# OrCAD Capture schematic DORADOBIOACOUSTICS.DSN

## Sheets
1 4 MiniWBT Wiring: size Custom; title: Dorado Bioacoustics System; rev: A; note: 100221282
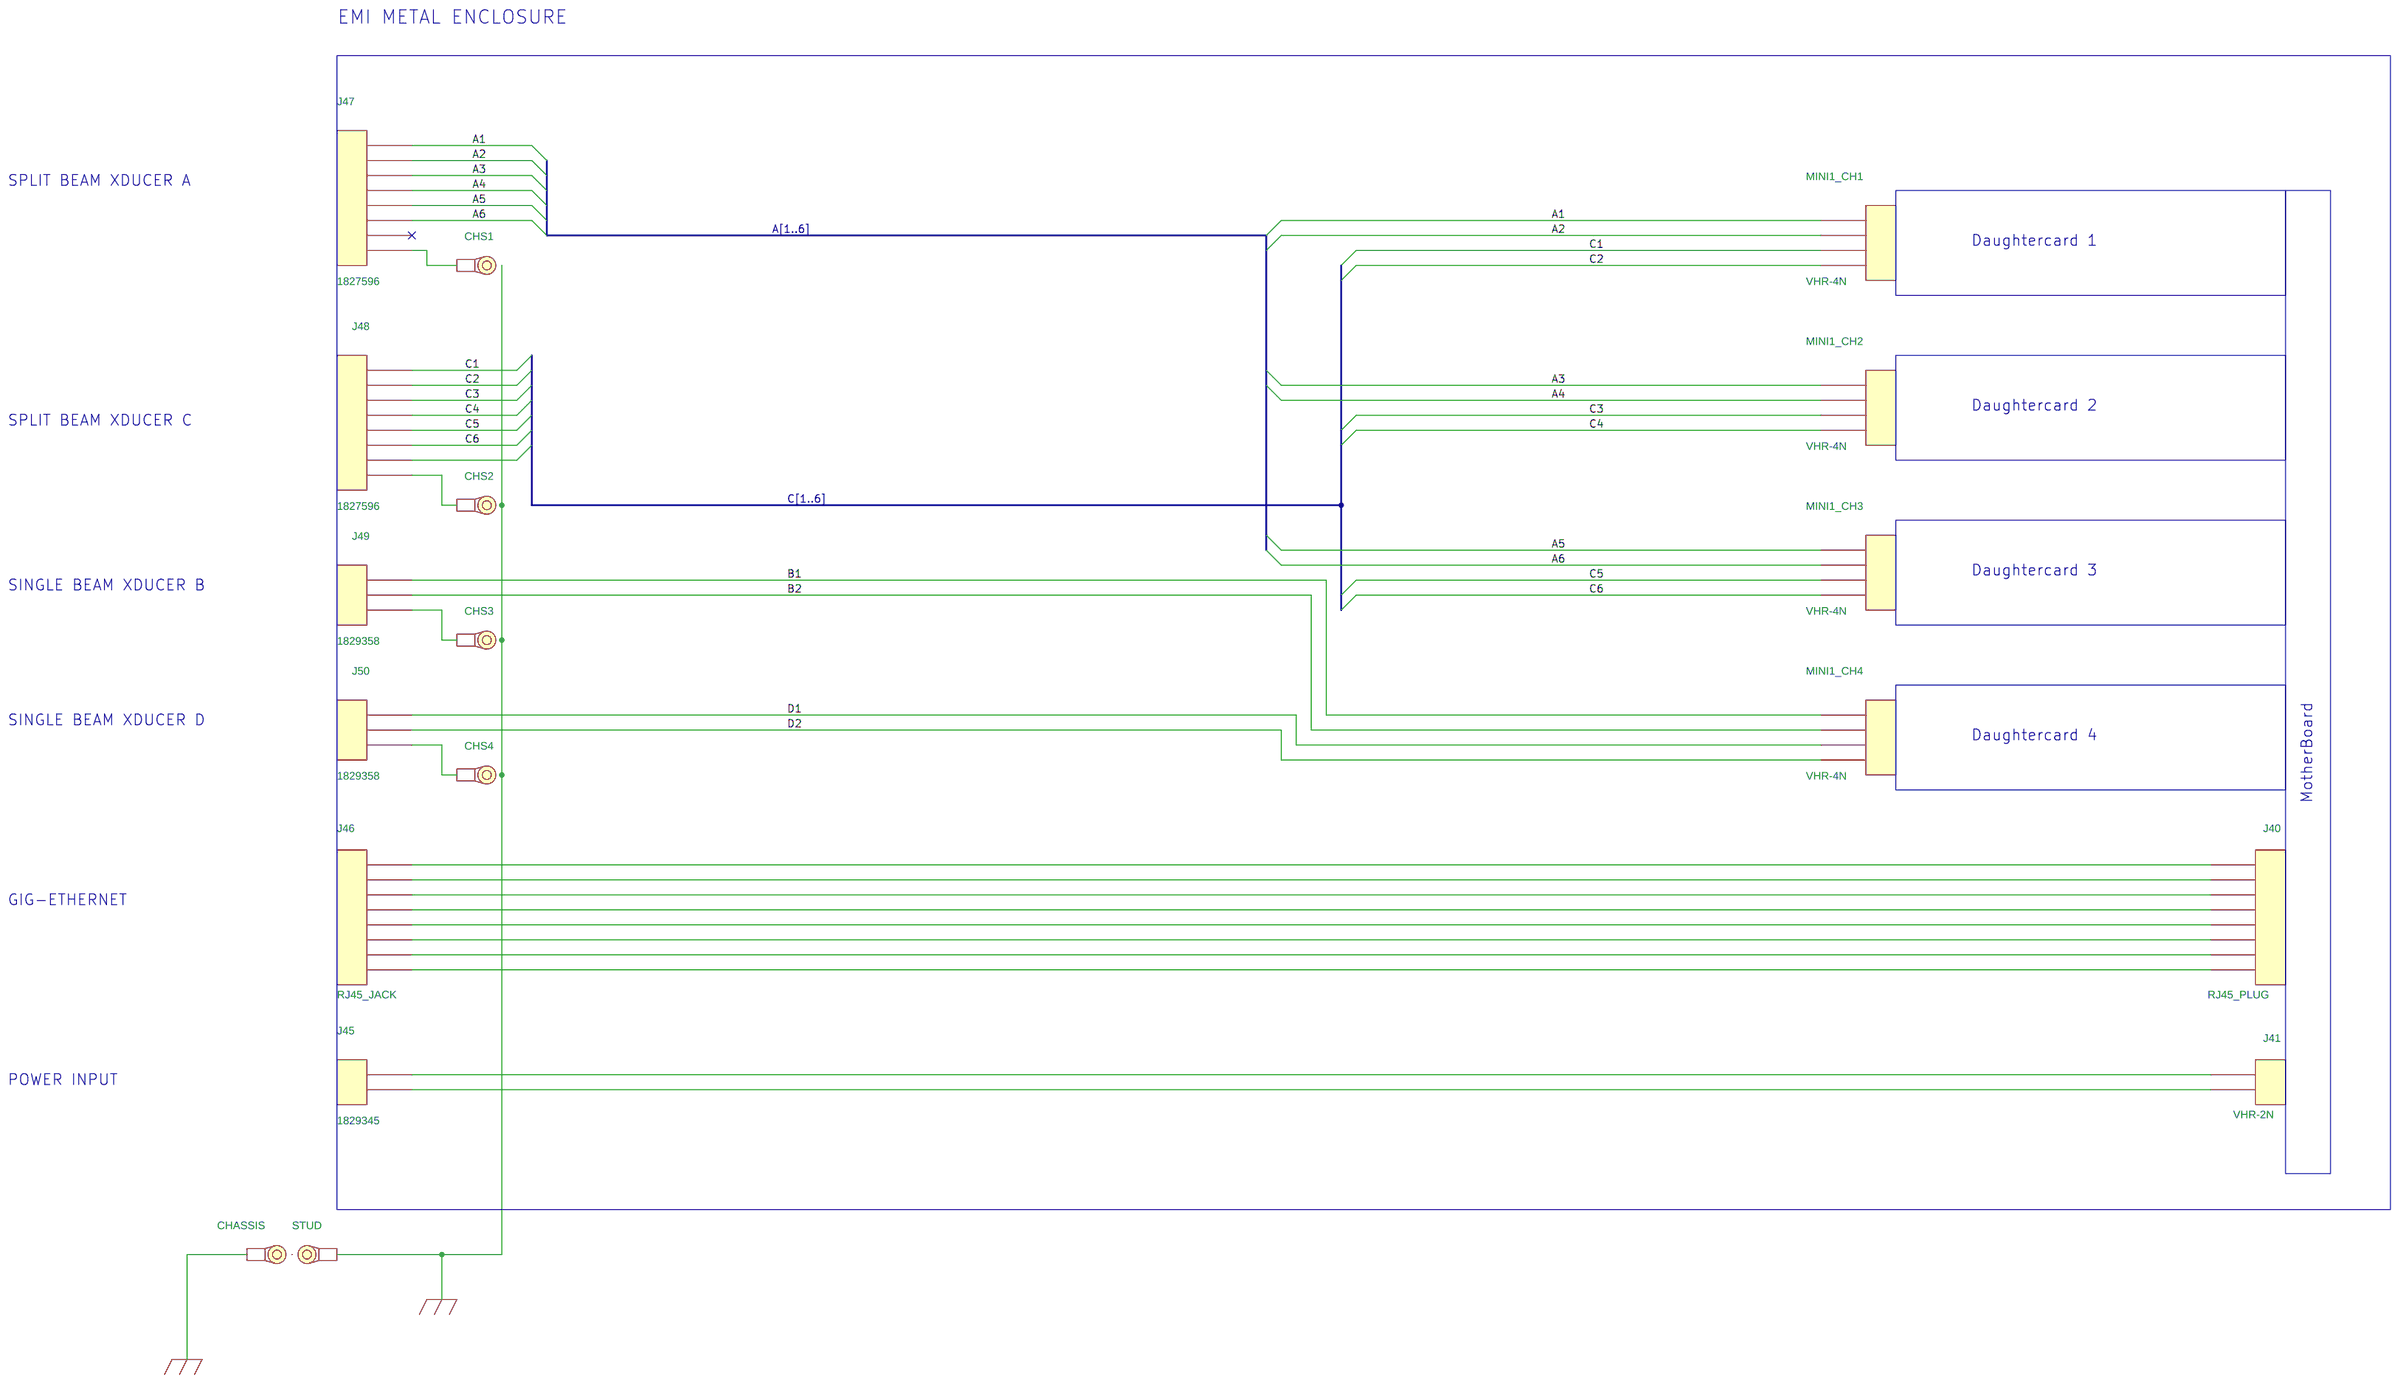
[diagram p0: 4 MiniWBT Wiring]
2 1 System Concept: size Custom; note: 100221222
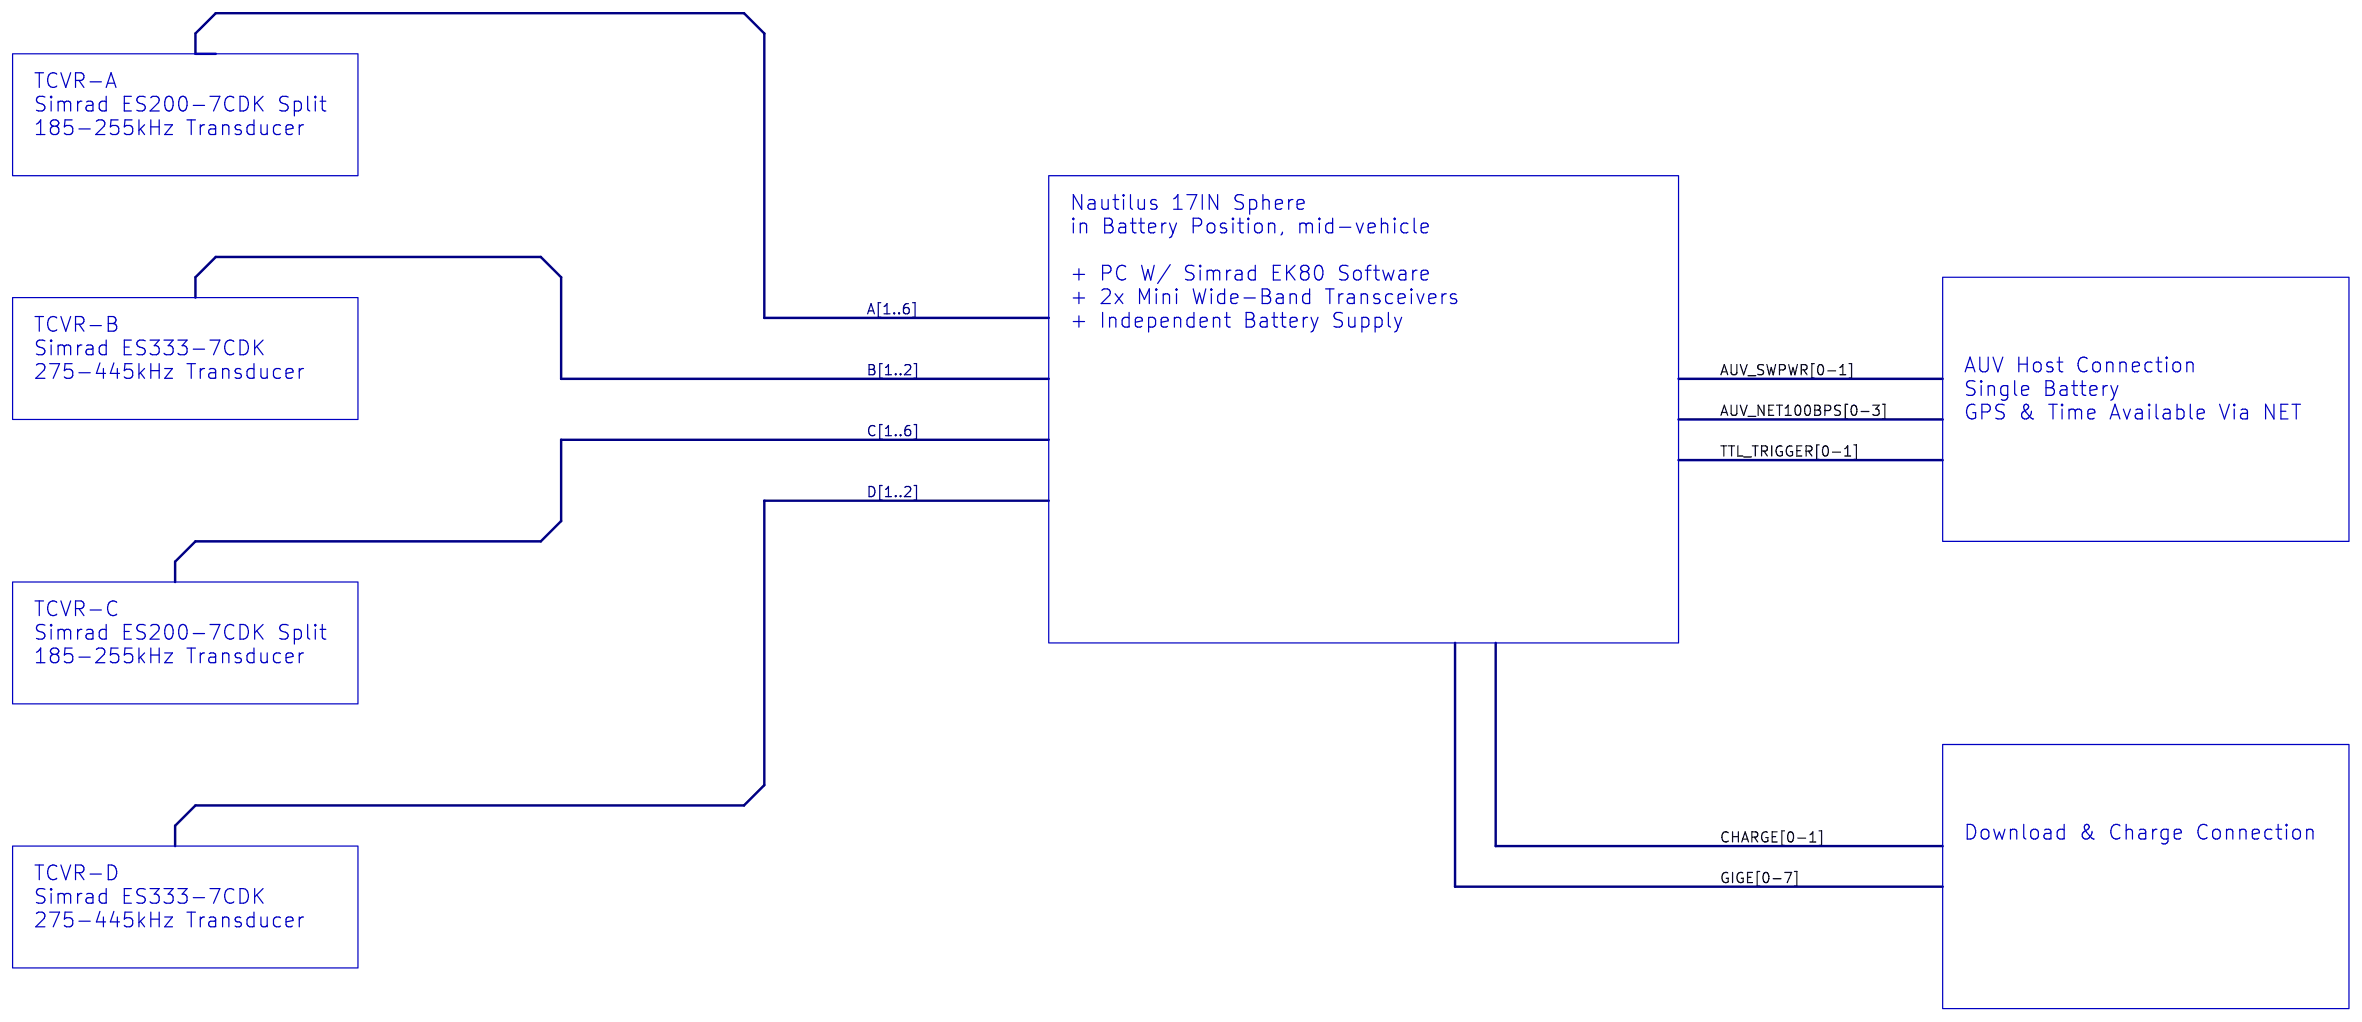
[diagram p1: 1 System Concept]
3 2 Subsea Cabling: size Custom; note: 100221222
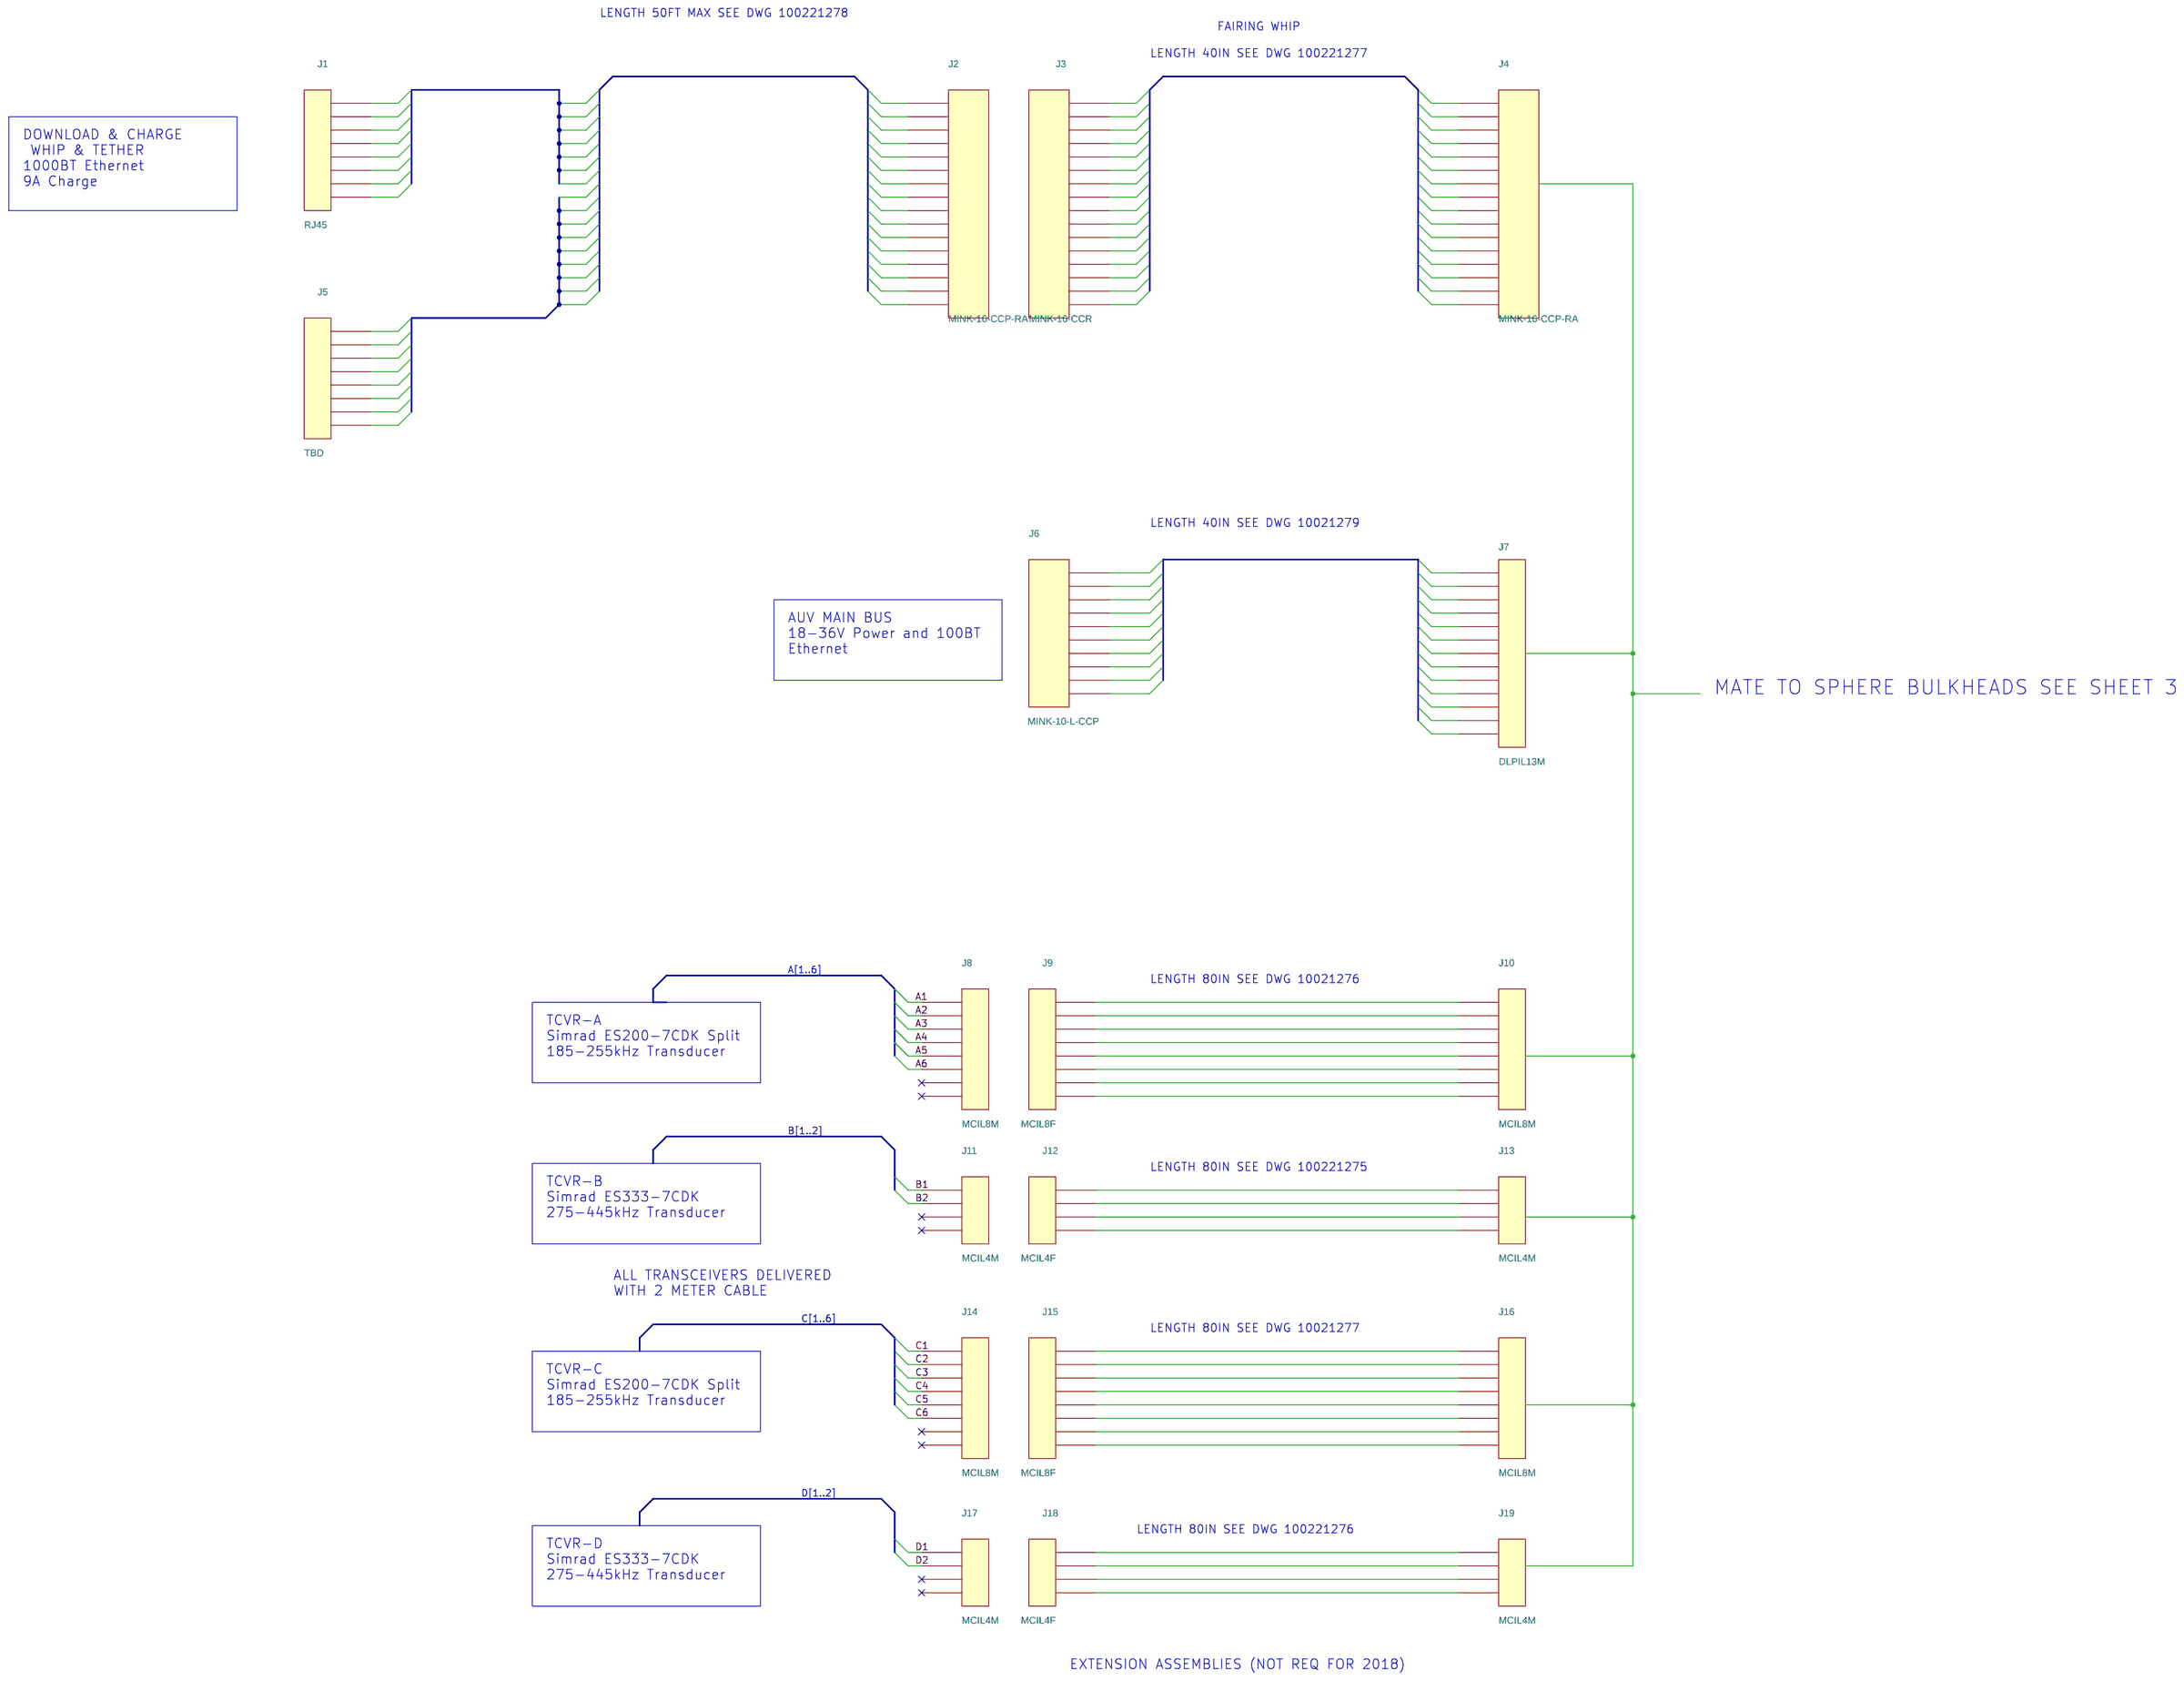
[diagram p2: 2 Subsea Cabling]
4 3 Sphere Wiring: size Custom; note: 100221222
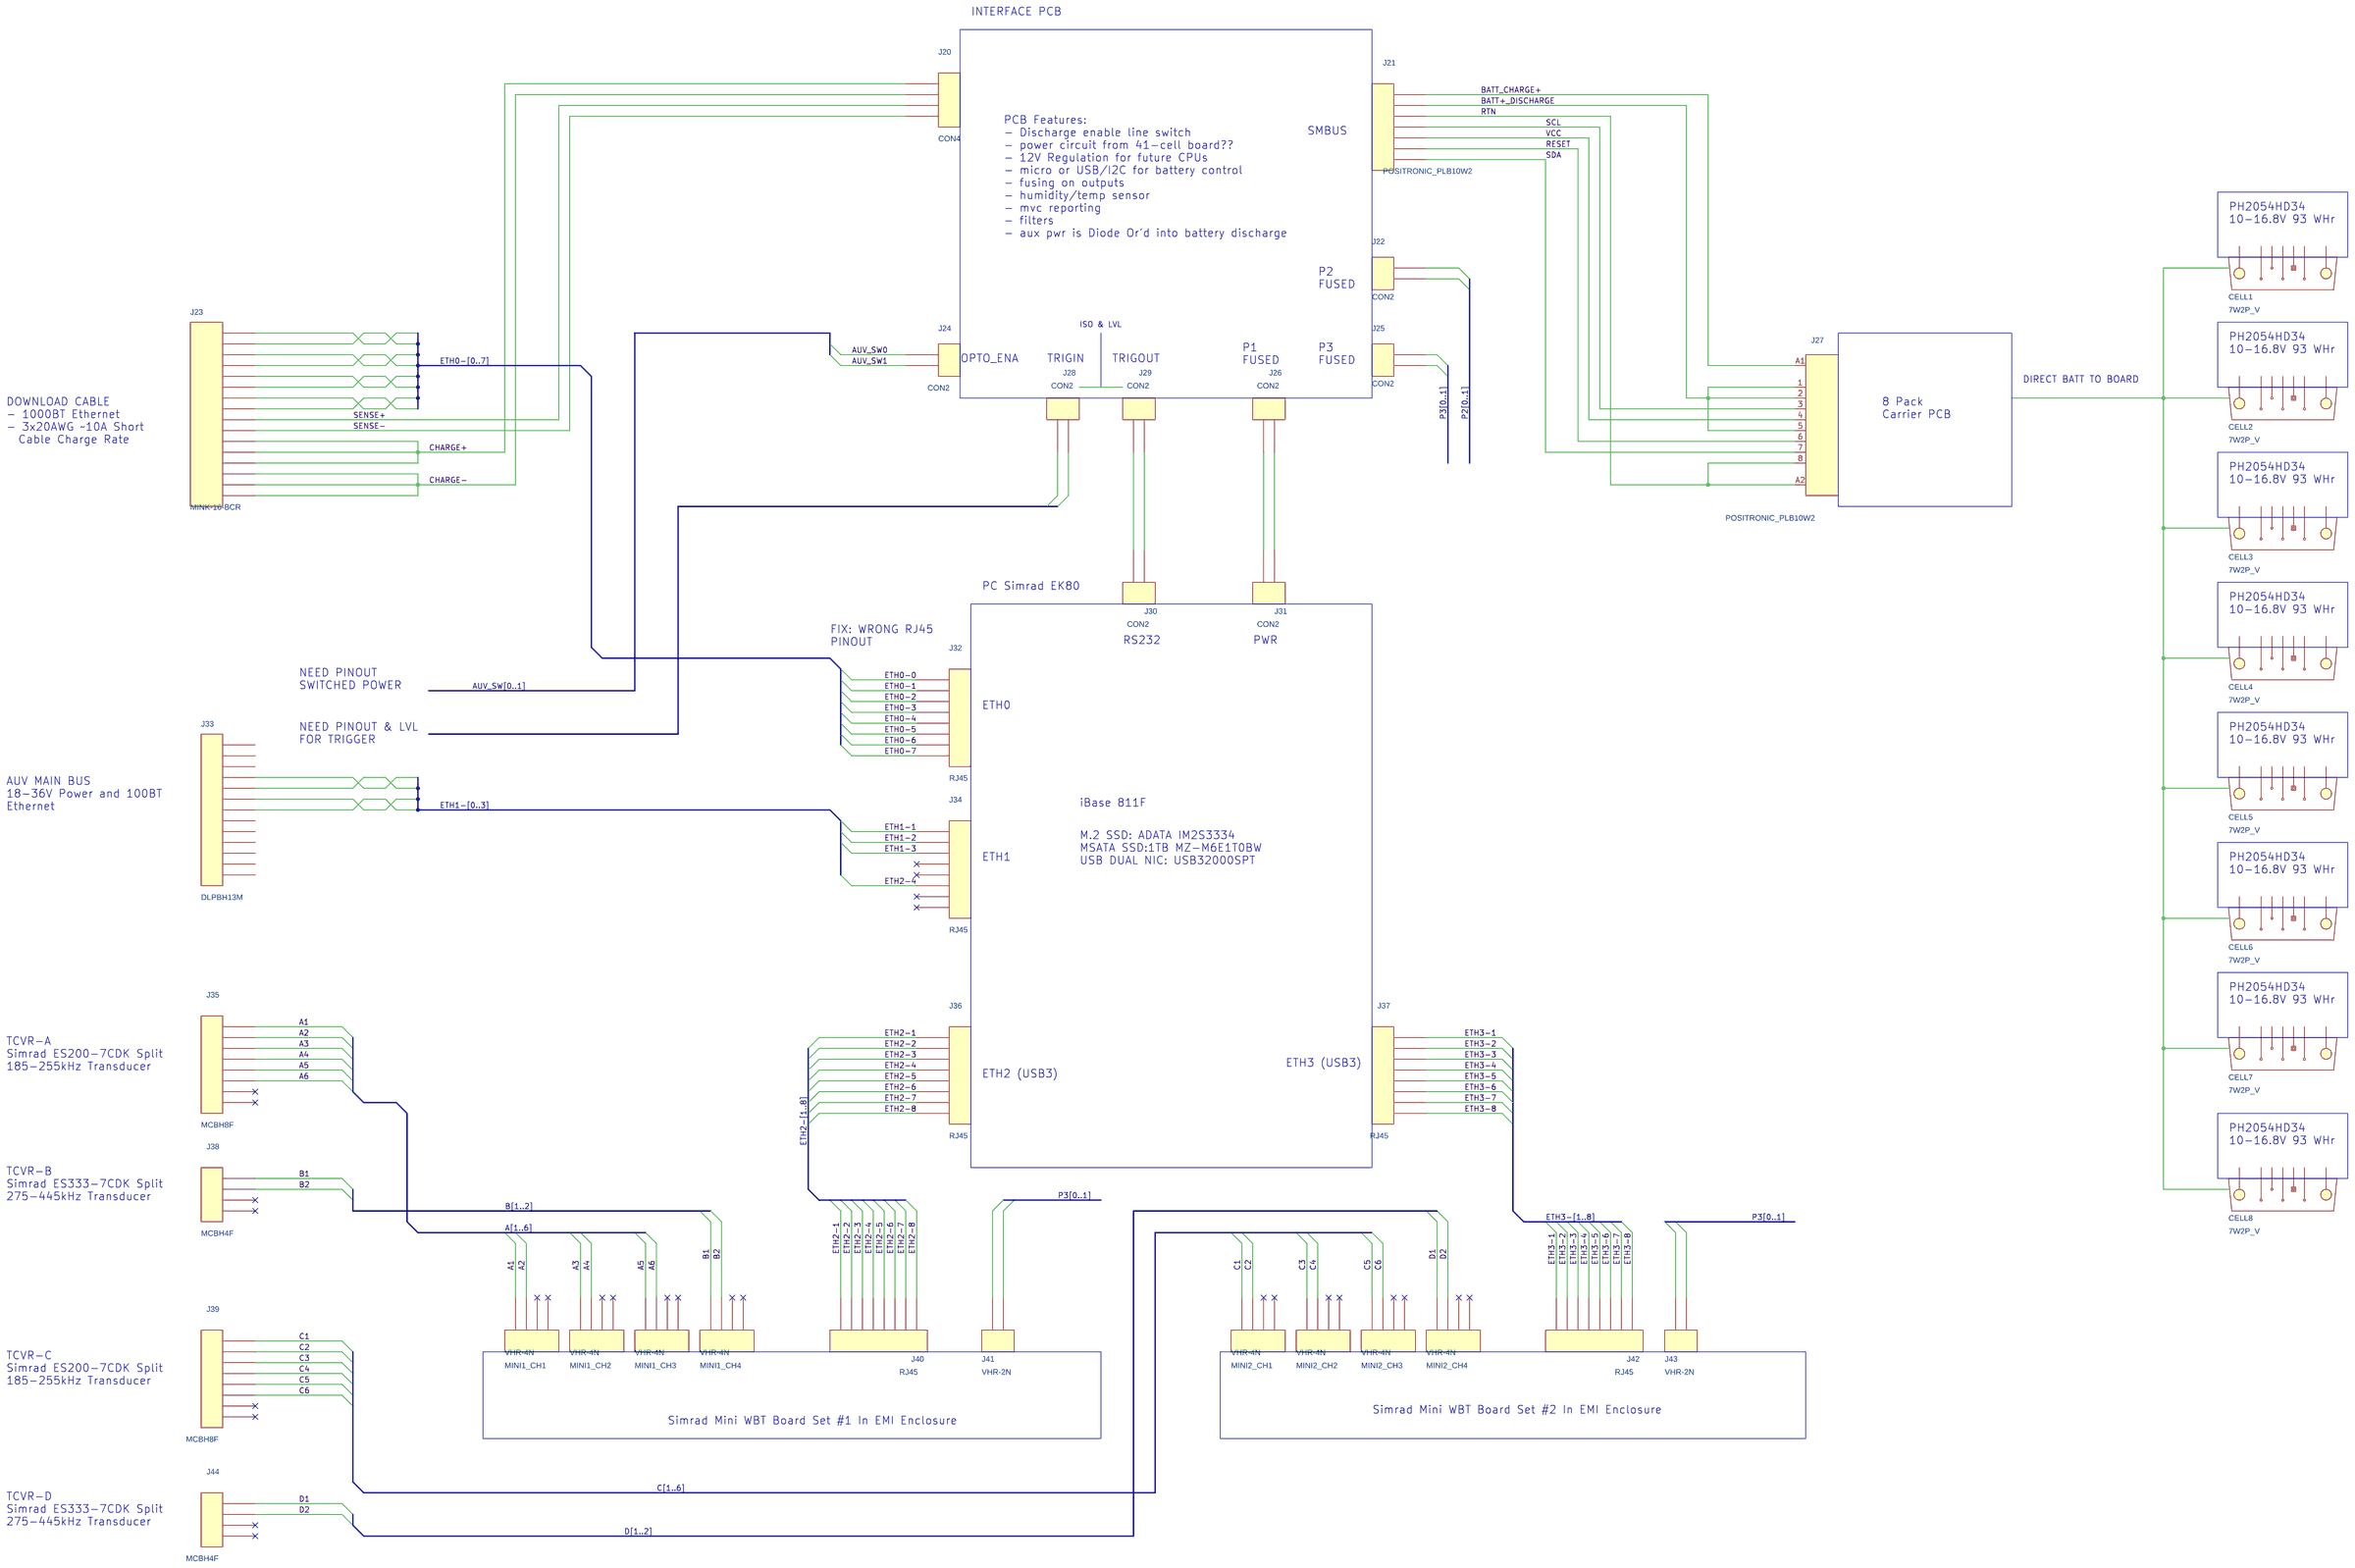
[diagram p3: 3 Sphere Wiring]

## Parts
sheet 2 Subsea Cabling
J1  RJ45
J2  MINK-16-CCP-RA
J3  MINK-16-CCR
J4  MINK-16-CCP-RA
J5  TBD
J6  MINK-10-L-CCP
J7  DLPIL13M
J8  MCIL8M
J9  MCIL8F
J10  MCIL8M
J11  MCIL4M
J12  MCIL4F
J13  MCIL4M
J14  MCIL8M
J15  MCIL8F
J16  MCIL8M
J17  MCIL4M
J18  MCIL4F
J19  MCIL4M
sheet 3 Sphere Wiring
CELL1  7W2P_V  [7W2P_V]
CELL2  7W2P_V  [7W2P_V]
CELL3  7W2P_V  [7W2P_V]
CELL4  7W2P_V  [7W2P_V]
CELL5  7W2P_V  [7W2P_V]
CELL6  7W2P_V  [7W2P_V]
CELL7  7W2P_V  [7W2P_V]
CELL8  7W2P_V  [7W2P_V]
J20  CON4
J21  POSITRONIC_PLB10W2
J22  CON2
J23  MINK-16-BCR
J24  CON2
J25  CON2
J26  CON2
J27  POSITRONIC_PLB10W2  [POSITRONIC_PLB10W2F400A1]
J28  CON2
J29  CON2
J30  CON2
J31  CON2
J32  RJ45
J33  DLPBH13M
J34  RJ45
J35  MCBH8F
J36  RJ45
J37  RJ45
J38  MCBH4F
J39  MCBH8F
J40  RJ45
J41  VHR-2N
J42  RJ45
J43  VHR-2N
J44  MCBH4F
MINI1_CH1  VHR-4N
MINI1_CH2  VHR-4N
MINI1_CH3  VHR-4N
MINI1_CH4  VHR-4N
MINI2_CH1  VHR-4N
MINI2_CH2  VHR-4N
MINI2_CH3  VHR-4N
MINI2_CH4  VHR-4N
sheet 4 MiniWBT Wiring
CHASSIS  320619  [UNASSIGNED]
CHS1  320619  [UNASSIGNED]
CHS2  320619  [UNASSIGNED]
CHS3  320619  [UNASSIGNED]
CHS4  320619  [UNASSIGNED]
J40#2  RJ45_PLUG
J41#2  VHR-2N
J45  1829345
J46  RJ45_JACK
J47  1827596
J48  1827596
J49  1829358
J50  1829358
MINI1_CH1#2  VHR-4N
MINI1_CH2#2  VHR-4N
MINI1_CH3#2  VHR-4N
MINI1_CH4#2  VHR-4N
STUD  320619  [UNASSIGNED]

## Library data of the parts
J1 J5 J8-J10 J14-J16 J32 J34-J37 J39 J40 J40#2 J42 J46-J48 = CON8
J2-J4 J23 = CON16
J6 = CON10
J7 J33 = CONN_FLEX_13
J11-J13 J17-J20 J38 J44 MINI1_CH1 MINI1_CH1#2 MINI1_CH2 MINI1_CH2#2 MINI1_CH3 MINI1_CH3#2 MINI1_CH4 MINI1_CH4#2 MINI2_CH1-MINI2_CH4 = CON4
CELL1-CELL8 = 7W2P_H: COMPFIXED: NO; COMPGROUP: 0; COMPHEIGHT: 488.000; COMPKEY: NO; COMPLOC: [2494.000,2674.000]; COMPLOCKED: NO; COMPROT: 0; COMPSIDE: BOT; DECOUPLER: NO; FPLIST: 7W2P_V,INSP_ENG_PH2059MB; MEMORY: NO; VENDOR: Mouser; VENDOR_PT_NO: 152-FM7W2P1-K120
J21 = CON7
J22 J24-J26 J28-J31 J41 J41#2 J43 J45 = CON2
J27 = POSITRONIC_PLB10W2: COMPFIXED: YES; COMPGROUP: 0; COMPHEIGHT: 606.000; COMPKEY: NO; COMPLOC: [2317.000,885.000]; COMPLOCKED: YES; COMPROT: 270; COMPSIDE: TOP; DECOUPLER: NO; FPLIST: POSITRONIC_PLB10W2F300A1_STRT; MEMORY: NO; VENDOR: Positronic; VENDOR_PT_NO: PLB10W2F300A1
CHASSIS CHS1-CHS4 STUD = BLUE_Ring_Terminal: CONN RING 14-16 AWG #6 BLUE PIDG; CLASS: IO; Depth_Tested: 0.170"; Manufacturer: TE Connectivity
J49 J50 = CON3

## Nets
GND_EARTH: CHASSIS.1 CHS1.2 CHS2.2 CHS3.2 CHS4.2 STUD.1
VCC: J21.5 J27.4
A1: J8.1
A1 (page 3 Sphere Wiring): J35.1 MINI1_CH1.1
A1 (page 4 MiniWBT Wiring): J47.1 MINI1_CH1#2.1
A2: J8.2
A2 (page 3 Sphere Wiring): J35.2 MINI1_CH1.2
A2 (page 4 MiniWBT Wiring): J47.2 MINI1_CH1#2.2
A3: J8.3
A3 (page 3 Sphere Wiring): J35.3 MINI1_CH2.1
A3 (page 4 MiniWBT Wiring): J47.3 MINI1_CH2#2.1
A4: J8.4
A4 (page 3 Sphere Wiring): J35.4 MINI1_CH2.2
A4 (page 4 MiniWBT Wiring): J47.4 MINI1_CH2#2.2
A5: J8.5
A5 (page 3 Sphere Wiring): J35.5 MINI1_CH3.1
A5 (page 4 MiniWBT Wiring): J47.5 MINI1_CH3#2.1
A6: J8.6
A6 (page 3 Sphere Wiring): J35.6 MINI1_CH3.2
A6 (page 4 MiniWBT Wiring): J47.6 MINI1_CH3#2.2
AUV_SW0: J24.1
AUV_SW1: J24.2
B1: J11.1
B1 (page 3 Sphere Wiring): J38.1 MINI1_CH4.1
B1 (page 4 MiniWBT Wiring): J49.1 MINI1_CH4#2.1
B2: J11.2
B2 (page 3 Sphere Wiring): J38.2 MINI1_CH4.2
B2 (page 4 MiniWBT Wiring): J49.2 MINI1_CH4#2.2
BATT+_DISCHARGE: J21.2 J27.1 J27.2 J27.5
BATT_CHARGE+: J21.1 J27.A1
C1: J14.1
C1 (page 3 Sphere Wiring): J39.1 MINI2_CH1.1
C1 (page 4 MiniWBT Wiring): J48.1 MINI1_CH1#2.3
C2: J14.2
C2 (page 3 Sphere Wiring): J39.2 MINI2_CH1.2
C2 (page 4 MiniWBT Wiring): J48.2 MINI1_CH1#2.4
C3: J14.3
C3 (page 3 Sphere Wiring): J39.3 MINI2_CH2.1
C3 (page 4 MiniWBT Wiring): J48.3 MINI1_CH2#2.3
C4: J14.4
C4 (page 3 Sphere Wiring): J39.4 MINI2_CH2.2
C4 (page 4 MiniWBT Wiring): J48.4 MINI1_CH2#2.4
C5: J14.5
C5 (page 3 Sphere Wiring): J39.5 MINI2_CH3.1
C5 (page 4 MiniWBT Wiring): J48.5 MINI1_CH3#2.3
C6: J14.6
C6 (page 3 Sphere Wiring): J39.6 MINI2_CH3.2
C6 (page 4 MiniWBT Wiring): J48.6 MINI1_CH3#2.4
CHARGE+: J20.1 J23.11 J23.12 J23.13
CHARGE-: J20.2 J23.14 J23.15 J23.16
D1: J17.1
D1 (page 3 Sphere Wiring): J44.1 MINI2_CH4.1
D1 (page 4 MiniWBT Wiring): J50.1 MINI1_CH4#2.3
D2: J17.2
D2 (page 3 Sphere Wiring): J44.2 MINI2_CH4.2
D2 (page 4 MiniWBT Wiring): J50.2 MINI1_CH4#2.4
ETH0-0: J32.1
ETH0-1: J32.2
ETH0-2: J32.3
ETH0-3: J32.4
ETH0-4: J32.5
ETH0-5: J32.6
ETH0-6: J32.7
ETH0-7: J32.8
ETH1-1: J34.1
ETH1-2: J34.2
ETH1-3: J34.3
ETH2-1: J36.1 J40.1
ETH2-2: J36.2 J40.2
ETH2-3: J36.3 J40.3
ETH2-4: J34.6 J36.4 J40.4
ETH2-5: J36.5 J40.5
ETH2-6: J36.6 J40.6
ETH2-7: J36.7 J40.7
ETH2-8: J36.8 J40.8
ETH3-1: J37.1 J42.1
ETH3-2: J37.2 J42.2
ETH3-3: J37.3 J42.3
ETH3-4: J37.4 J42.4
ETH3-5: J37.5 J42.5
ETH3-6: J37.6 J42.6
ETH3-7: J37.7 J42.7
ETH3-8: J37.8 J42.8
RESET: J21.6 J27.6
RTN: J21.3 J27.8 J27.A2
SCL: J21.4 J27.3
SDA: J21.7 J27.7
SENSE+: J20.3 J23.9
SENSE-: J20.4 J23.10
N03367: J9.1 J10.1
N03369: J9.2 J10.2
N03371: J9.3 J10.3
N03373: J9.4 J10.4
N03375: J9.5 J10.5
N03377: J9.6 J10.6
N03379: J9.7 J10.7
N03381: J9.8 J10.8
N03407: J12.1 J13.1
N03409: J12.2 J13.2
N03411: J12.3 J13.3
N03413: J12.4 J13.4
N03439: J15.1 J16.1
N03441: J15.2 J16.2
N03443: J15.3 J16.3
N03445: J15.4 J16.4
N03447: J15.5 J16.5
N03449: J15.6 J16.6
N03451: J15.7 J16.7
N03453: J15.8 J16.8
N03479: J18.1 J19.1
N03481: J18.2 J19.2
N03483: J18.3 J19.3
N03485: J18.4 J19.4
N10600770: J29.1 J30.1
N10600772: J29.2 J30.2
N10600808: J26.1 J31.1
N10600810: J26.2 J31.2
N10652401: J41#2.1 J45.1
N10652403: J41#2.2 J45.2
N10652475: J40#2.1 J46.1
N10652477: J40#2.2 J46.2
N10652479: J40#2.3 J46.3
N10652481: J40#2.4 J46.4
N10652483: J40#2.5 J46.5
N10652485: J40#2.6 J46.6
N10652487: J40#2.7 J46.7
N10652489: J40#2.8 J46.8
N10652671: CHS4.1 J50.3
N10652679: CHS2.1 J48.8
N10652689: CHS3.1 J49.3
N10652701: CHS1.1 J47.8
N10658006: CHASSIS.2 STUD.2

Not connected (* = marked no-connect by the designer): CELL1 1 2 3 4 5 A1 A2; CELL2 1 2 3 4 5 A1 A2; CELL3 1 2 3 4 5 A1 A2; CELL4 1 2 3 4 5 A1 A2; CELL5 1 2 3 4 5 A1 A2; CELL6 1 2 3 4 5 A1 A2; CELL7 1 2 3 4 5 A1 A2; CELL8 1 2 3 4 5 A1 A2; J1 1 2 3 4 5 6 7 8; J2 1 2 3 4 5 6 7 8 9 10 11 12 13 14 15 16; J3 1 2 3 4 5 6 7 8 9 10 11 12 13 14 15 16; J4 1 2 3 4 5 6 7 8 9 10 11 12 13 14 15 16; J5 1 2 3 4 5 6 7 8; J6 1 2 3 4 5 6 7 8 9 10; J7 1 2 3 4 5 6 7 8 9 10 11 12 13; J8 7* 8*; J11 3* 4*; J14 7* 8*; J17 3* 4*; J22 1 2; J23 1 2 3 4 5 6 7 8; J25 1 2; J28 1 2; J33 1 2 3 4 5 6 7 8 9 10 11 12 13; J34 4* 5* 7* 8*; J35 7* 8*; J38 3* 4*; J39 7* 8*; J41 1 2; J43 1 2; J44 3* 4*; J47 7*; J48 7; MINI1_CH1 3* 4*; MINI1_CH2 3* 4*; MINI1_CH3 3* 4*; MINI1_CH4 3* 4*; MINI2_CH1 3* 4*; MINI2_CH2 3* 4*; MINI2_CH3 3* 4*; MINI2_CH4 3* 4*

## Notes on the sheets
sheet 1
- EMI METAL ENCLOSURE
- SPLIT BEAM XDUCER A
- Daughtercard 1
- Daughtercard 2
- SPLIT BEAM XDUCER C
- Daughtercard 3
- SINGLE BEAM XDUCER B
- SINGLE BEAM XDUCER D
- Daughtercard 4
- MotherBoard
- GIG-ETHERNET
- POWER INPUT
sheet 2
- TCVR-A
  Simrad ES200-7CDK Split
  185-255kHz Transducer
- Nautilus 17IN Sphere
  in Battery Position, mid-vehicle
  + PC W/ Simrad EK80 Software
  + 2x Mini Wide-Band Transceivers
  + Independent Battery Supply
- TCVR-B
  Simrad ES333-7CDK
  275-445kHz Transducer
- AUV Host Connection
  Single Battery
  GPS & Time Available Via NET
- TCVR-C
  Simrad ES200-7CDK Split
  185-255kHz Transducer
- Download & Charge Connection
- TCVR-D
  Simrad ES333-7CDK
  275-445kHz Transducer
sheet 3
- LENGTH 50FT MAX SEE DWG 100221278
- FAIRING WHIP
- LENGTH 40IN SEE DWG 100221277
- DOWNLOAD & CHARGE
   WHIP & TETHER
  1000BT Ethernet
  9A Charge
- LENGTH 40IN SEE DWG 10021279
- AUV MAIN BUS
  18-36V Power and 100BT
  Ethernet
- MATE TO SPHERE BULKHEADS SEE SHEET 3
- LENGTH 80IN SEE DWG 10021276
- TCVR-A
  Simrad ES200-7CDK Split
  185-255kHz Transducer
- LENGTH 80IN SEE DWG 100221275
- TCVR-B
  Simrad ES333-7CDK
  275-445kHz Transducer
- ALL TRANSCEIVERS DELIVERED
  WITH 2 METER CABLE
- LENGTH 80IN SEE DWG 10021277
- TCVR-C
  Simrad ES200-7CDK Split
  185-255kHz Transducer
- LENGTH 80IN SEE DWG 100221276
- TCVR-D
  Simrad ES333-7CDK
  275-445kHz Transducer
- EXTENSION ASSEMBLIES (NOT REQ FOR 2018)
sheet 4
- INTERFACE PCB
- PCB Features:
  - Discharge enable line switch
  - power circuit from 41-cell board??
  - 12V Regulation for future CPUs
  - micro or USB/I2C for battery control
  - fusing on outputs
  - humidity/temp sensor
  - mvc reporting
  - filters
  - aux pwr is Diode Or'd into battery discharge
- SMBUS
- PH2054HD34
  10-16.8V 93 WHr
- P2
  FUSED
- ISO & LVL
- PH2054HD34
  10-16.8V 93 WHr
- P1
  FUSED
- P3
  FUSED
- OPTO_ENA
- TRIGIN
- TRIGOUT
- DIRECT BATT TO BOARD
- DOWNLOAD CABLE
  - 1000BT Ethernet
  - 3x20AWG ~10A Short
    Cable Charge Rate
- 8 Pack
  Carrier PCB
- PH2054HD34
  10-16.8V 93 WHr
- PC Simrad EK80
- PH2054HD34
  10-16.8V 93 WHr
- FIX: WRONG RJ45
  PINOUT
- RS232
- PWR
- NEED PINOUT
  SWITCHED POWER
- ETH0
- NEED PINOUT & LVL
  FOR TRIGGER
- PH2054HD34
  10-16.8V 93 WHr
- AUV MAIN BUS
  18-36V Power and 100BT
  Ethernet
- iBase 811F
- M.2 SSD: ADATA IM2S3334
  MSATA SSD:1TB MZ-M6E1T0BW
  USB DUAL NIC: USB32000SPT
- ETH1
- PH2054HD34
  10-16.8V 93 WHr
- PH2054HD34
  10-16.8V 93 WHr
- TCVR-A
  Simrad ES200-7CDK Split
  185-255kHz Transducer
- ETH3 (USB3)
- ETH2 (USB3)
- PH2054HD34
  10-16.8V 93 WHr
- TCVR-B
  Simrad ES333-7CDK Split
  275-445kHz Transducer
- TCVR-C
  Simrad ES200-7CDK Split
  185-255kHz Transducer
- Simrad Mini WBT Board Set #2 In EMI Enclosure
- Simrad Mini WBT Board Set #1 In EMI Enclosure
- TCVR-D
  Simrad ES333-7CDK Split
  275-445kHz Transducer
